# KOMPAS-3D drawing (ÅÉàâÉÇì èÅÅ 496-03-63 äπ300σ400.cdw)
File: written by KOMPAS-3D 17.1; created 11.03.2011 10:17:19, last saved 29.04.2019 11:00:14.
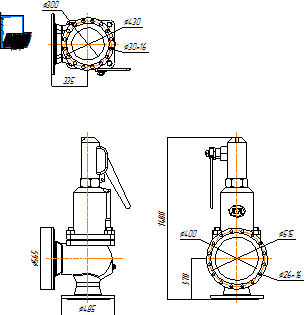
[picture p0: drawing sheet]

Sheet 1: A4, portrait

Title block, sheet 1: name: Прегран Ду300х400; material: Внимание! Данный продукт является объектом авторского права ООО «Торговый Дом АДЛ». / Запрещается изменение, копирование, распространение / (в том числе путем копирования на другие сайты и ресурсы в Интернете) / или любое иное использование информации и объектов без предварительного / согласия правообладателя (ООО «Торговый Дом АДЛ»).; scale: 1:1; sheets: 1; organisation: ООО "Торговый дом АДЛ"; sheet format: A4; stored path: C:\Users\tra\Desktop\2д чертежи\Предохранительные клапаны ПРЕГРАН\ПРЕГРАН 496\ПРЕГРАН КПП 496-03-63\KOMPAS 2D\Прегран Ду300х400.cdw

Views: Спереди 1, Проекционный вид 2, Проекционный вид 3
Dimensions and other numbers on the sheet: 335; 430; 30; 300; 1480; 370; 485; 565; 515; 26; 400; 1:1; 1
